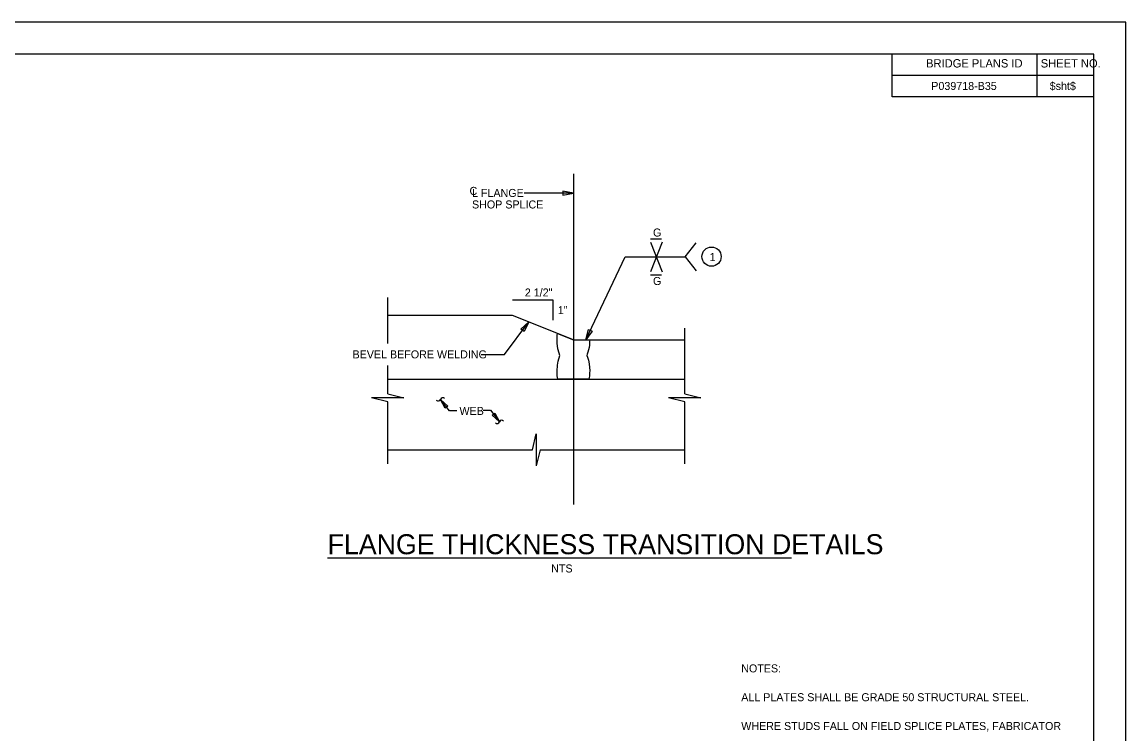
# Model space of a CAD drawing. Extents: x -448.1 to -400, y -140.7 to -111.4.
# Drawn here: x -423.13 to -400.13, y -126.19 to -111.36 of the extents above; entities that cross this region are included whole.
import ezdxf

# ---------------------------------------------------------------- set-up
doc = ezdxf.new("R2010")
doc.units = 0
for name, color, linetype in [('BR_AUTO DIMENSION', 7, 'Continuous'), ('BR_BORDER LINES', 7, 'Continuous'), ('BR_CENTER LINES', 7, 'Continuous'), ('BR_STRUCTURAL STEEL', 7, 'Continuous'), ('BR_TEXT', 7, 'Continuous'), ('Default', 7, 'Continuous'), ('Level 31', 7, 'Continuous')]:
    doc.layers.add(name, color=color, linetype=linetype)

msp = doc.modelspace()

# ---------------------------------------------------------------- linework, layer by layer
at = {"layer": 'BR_AUTO DIMENSION'}
for p, q in [((-410.034, -115.88), (-409.811, -115.88)), ((-409.797, -115.949), (-410.035, -116.563)), ((-410.035, -115.949), (-409.797, -116.563)), ((-409.318, -116.256), (-409.089, -115.964)), ((-411.386, -117.981), (-410.563, -116.256)), ((-410.563, -116.256), (-409.318, -116.256)), ((-409.318, -116.256), (-409.089, -116.547)), ((-410.034, -116.631), (-409.811, -116.631)), ((-413.079, -118.289), (-412.572, -117.609)), ((-413.565, -118.289), (-413.079, -118.289)), ((-414.227, -119.464), (-414.415, -119.222)), ((-414.074, -119.464), (-414.227, -119.464)), ((-413.522, -119.45), (-413.369, -119.45)), ((-413.369, -119.45), (-413.181, -119.691))]:
    msp.add_line(p, q, dxfattribs=at)
msp.add_lwpolyline([(-411.644, -114.928), (-412.666, -114.928)], dxfattribs=at)
for points in [[(-411.861, -114.97), (-411.644, -114.928), (-411.861, -114.886)], [(-412.735, -117.758), (-412.572, -117.61), (-412.668, -117.808)], [(-411.255, -117.803), (-411.386, -117.981), (-411.331, -117.767)], [(-414.259, -119.365), (-414.314, -119.408), (-414.415, -119.222)], [(-413.337, -119.548), (-413.282, -119.506), (-413.181, -119.691)]]:
    msp.add_lwpolyline(points, close=True, dxfattribs=at)
at = {"layer": 'BR_BORDER LINES'}
for p, q in [((-400.801, -112.031), (-445.689, -112.031)), ((-405.004, -112.92), (-405.004, -112.031)), ((-401.982, -112.92), (-401.982, -112.031)), ((-400.801, -140.031), (-400.801, -112.031)), ((-405.004, -112.47), (-400.801, -112.47)), ((-401.982, -112.47), (-400.801, -112.47)), ((-400.801, -112.92), (-405.004, -112.92))]:
    msp.add_line(p, q, dxfattribs=at)
at = {"layer": 'BR_CENTER LINES'}
msp.add_line((-411.644, -114.523), (-411.644, -121.412), dxfattribs=at)
at = {"layer": 'BR_STRUCTURAL STEEL'}
for p, q in [((-412.911, -117.474), (-415.512, -117.474)), ((-411.644, -117.981), (-412.911, -117.474)), ((-411.644, -117.981), (-409.323, -117.981)), ((-415.512, -118.8), (-409.323, -118.8))]:
    msp.add_line(p, q, dxfattribs=at)
at = {"layer": 'BR_TEXT'}
msp.add_line((-416.765, -122.521), (-407.1, -122.521), dxfattribs=at)
msp.add_circle((-408.765, -116.249), 0.2, dxfattribs=at)
at = {"layer": 'Default'}
for p, q in [((-415.512, -118.058), (-415.512, -117.101)), ((-412.067, -117.153), (-412.911, -117.153)), ((-412.067, -117.572), (-412.067, -117.153)), ((-409.323, -119.108), (-409.323, -117.74)), ((-415.512, -119.108), (-415.512, -118.518)), ((-415.512, -119.108), (-415.177, -119.189)), ((-409.323, -119.108), (-408.987, -119.189)), ((-415.512, -119.27), (-415.848, -119.189)), ((-415.177, -119.189), (-415.848, -119.189)), ((-415.512, -120.564), (-415.512, -119.27)), ((-409.323, -119.27), (-409.659, -119.189)), ((-408.987, -119.189), (-409.659, -119.189)), ((-409.323, -120.564), (-409.323, -119.27)), ((-412.498, -120.274), (-412.418, -119.938)), ((-412.418, -119.938), (-412.418, -120.609)), ((-415.512, -120.274), (-412.498, -120.274)), ((-412.337, -120.274), (-412.418, -120.609)), ((-412.337, -120.274), (-409.323, -120.274))]:
    msp.add_line(p, q, dxfattribs=at)
msp.add_lwpolyline([(-411.319, -118.8), (-411.969, -118.8), (-411.979, -118.733), (-411.984, -118.635), (-411.977, -118.512), (-411.961, -118.425), (-411.924, -118.307), (-411.942, -118.257), (-411.965, -118.171), (-411.982, -118.049), (-411.983, -117.94), (-411.979, -117.878), (-411.975, -117.848), (-411.644, -117.981), (-411.304, -117.981), (-411.305, -118.023), (-411.311, -118.093), (-411.318, -118.142), (-411.328, -118.192), (-411.341, -118.241), (-411.353, -118.278), (-411.364, -118.307), (-411.35, -118.345), (-411.331, -118.408), (-411.316, -118.483), (-411.307, -118.558), (-411.304, -118.623), (-411.305, -118.673), (-411.309, -118.734), (-411.315, -118.774), (-411.319, -118.8)], close=True, dxfattribs=at)
for centre, start, end in [((-414.461, -119.207), 219.9477, 342.4119), ((-414.368, -119.237), 39.9477, 162.4119), ((-413.228, -119.677), 219.9477, 342.4119), ((-413.135, -119.706), 39.9477, 162.4119)]:
    msp.add_arc(centre, 0.0488, start, end, dxfattribs=at)
at = {"layer": 'Level 31'}
msp.add_lwpolyline([(-448.133, -140.698), (-400.133, -140.698), (-400.133, -111.364), (-448.133, -111.364)], close=True, dxfattribs=at)

# ---------------------------------------------------------------- texts
at = {"layer": 'BR_TEXT'}
for s, height, p in [('BRIDGE PLANS ID', 0.17333, (-404.296, -112.31)), ('SHEET NO.', 0.1733, (-401.908, -112.31)), ('P039718-B35', 0.16667, (-404.188, -112.778)), ('$sht$', 0.1667, (-401.721, -112.778)), ('C', 0.167, (-413.807, -114.964)), ('L FLANGE', 0.1667, (-413.755, -115.006)), ('SHOP SPLICE', 0.16667, (-413.755, -115.246)), ('G', 0.167, (-409.985, -115.831)), ('1', 0.167, (-408.807, -116.341)), ('G', 0.167, (-409.985, -116.84)), ('2 1/2"', 0.1667, (-412.655, -117.079)), ('1"', 0.1667, (-411.968, -117.447)), ('BEVEL BEFORE WELDING', 0.16667, (-416.244, -118.368)), ('WEB', 0.1667, (-414.016, -119.546)), ('FLANGE THICKNESS TRANSITION DETAILS', 0.41667, (-416.763, -122.447)), ('NTS', 0.1667, (-412.106, -122.827)), ('NOTES:', 0.1667, (-408.147, -124.908)), ('ALL PLATES SHALL BE GRADE 50 STRUCTURAL STEEL.', 0.16667, (-408.147, -125.508)), ('WHERE STUDS FALL ON FIELD SPLICE PLATES, FABRICATOR', 0.16667, (-408.147, -126.108))]:
    msp.add_text(s, height=height, dxfattribs=at).set_placement(p)

doc.saveas('drawing.dxf')
